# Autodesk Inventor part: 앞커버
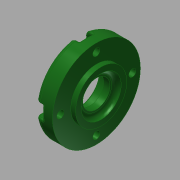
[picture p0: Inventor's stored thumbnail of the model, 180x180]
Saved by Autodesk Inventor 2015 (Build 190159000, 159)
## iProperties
Created: 2015-11
Part Number: 앞커버
Material: 알루미늄 6061
Document SubType Name: Modeling
Designer: mduedu
Density: 1 g/cm^3
Appearance: 매끄러움 - 짙은 산림 녹색
Author: mduedu
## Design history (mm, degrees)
sketch "스케치1"
  geometry: L1 (-7, 0)-(7, 0); L2 (-7, 0)-(-7, 27.5); L3 (-7, 27.5)-(4, 27.5); L4 (4, 27.5)-(4, 16); L5 (4, 16)-(7, 16); L6 (7, 16)-(7, 0); 2 further points
  constraints: 12 end point, 3 perpendicular, 2 parallel, 1 coincident, 1 horizontal, 1 midpoint
  dimensions: "d0" = 14 distance of L1.start L1.end; "d1" = 55 diameter of L3 L1; "d2" = 3 distance of L4.end L5.end; "d3" = 32 diameter of L5 L1
revolve "회전1" sketch "스케치1" stored, may be unused: angle "d4" = 90 deg
hole "구멍1" diameter "d7" = 25; stored, may be unused: countersink angle "d11" = 90 deg, drill point angle "d13" = 0 deg; dims "d5" = 10, "d6" = 10, "d8" = 6, "d9" = 4, "d10" = 2, "d12" = 3
hole "구멍2" diameter "d16" = 25; stored, may be unused: countersink angle "d20" = 90 deg, drill point angle "d22" = 0 deg; dims "d17" = 6, "d18" = 4, "d19" = 2, "d21" = 7, "d63" = 10, "d64" = 10
hole "구멍3" diameter "d25" = 17; stored, may be unused: countersink angle "d29" = 90 deg, drill point angle "d31" = 0 deg; dims "d23" = 10, "d24" = 10, "d26" = 6, "d27" = 4, "d28" = 2, "d30" = 4.2
chamfer "모따기1" distance "d32" = 0.6; stored, may be unused: second distance "d33" = 2, angle "d34" = 30 deg
fillet "모깎기1" dims "d35" = 0.3
fillet "모깎기2" dims "d36" = 3
fillet "모깎기3" dims "d37" = 3
sketch "스케치2" dims "d39" = 45
  geometry: C1 r 12.846 at (0, 0) reference; C2 r 24.5 at (0, 0) reference; 6 further points
  constraints: 2 vertical alignment, 1 coincident, 7 other
  dimensions: "d42" = 360 deg dimension on point (0, 0) point (0, 22.5) (derived)
sketch "스케치3"
  geometry: 8 further points
  constraints: 4 coincident
hole "구멍4" sketch "스케치3" at (-22.5, 0), (0, -22.5), (22.5, 0), (0, 22.5) diameter "d44" = 4.5; stored, may be unused: countersink angle "d48" = 90 deg, drill point angle "d50" = 0 deg; dims "d45" = 6, "d46" = 8, "d47" = 4.6, "d49" = 8
sketch "스케치4"
  geometry: L1 (-4, 0)-(-4, -4.708); L2 (4, 0)-(4, -4.708); A1 r 4 centre (0, 0) between (-4, 0) and (4, 0) reference; A2 r 27.5 centre (0, 22.5) between (-4, -4.708) and (4, -4.708) reference; 3 further points
  constraints: 4 end point, 4 point on circle, 2 tangent, 1 parallel, 1 vertical
extrude "돌출1" cut sketch "스케치4" stored distance "d51" = 0; taper "d52" = 0 deg
fillet "모깎기5" dims "d56" = 0.3
fillet "모깎기6" dims "d57" = 1
node "솔리드1"
pattern_circular "원형 패턴1" dims angle "d54" = 360 deg
